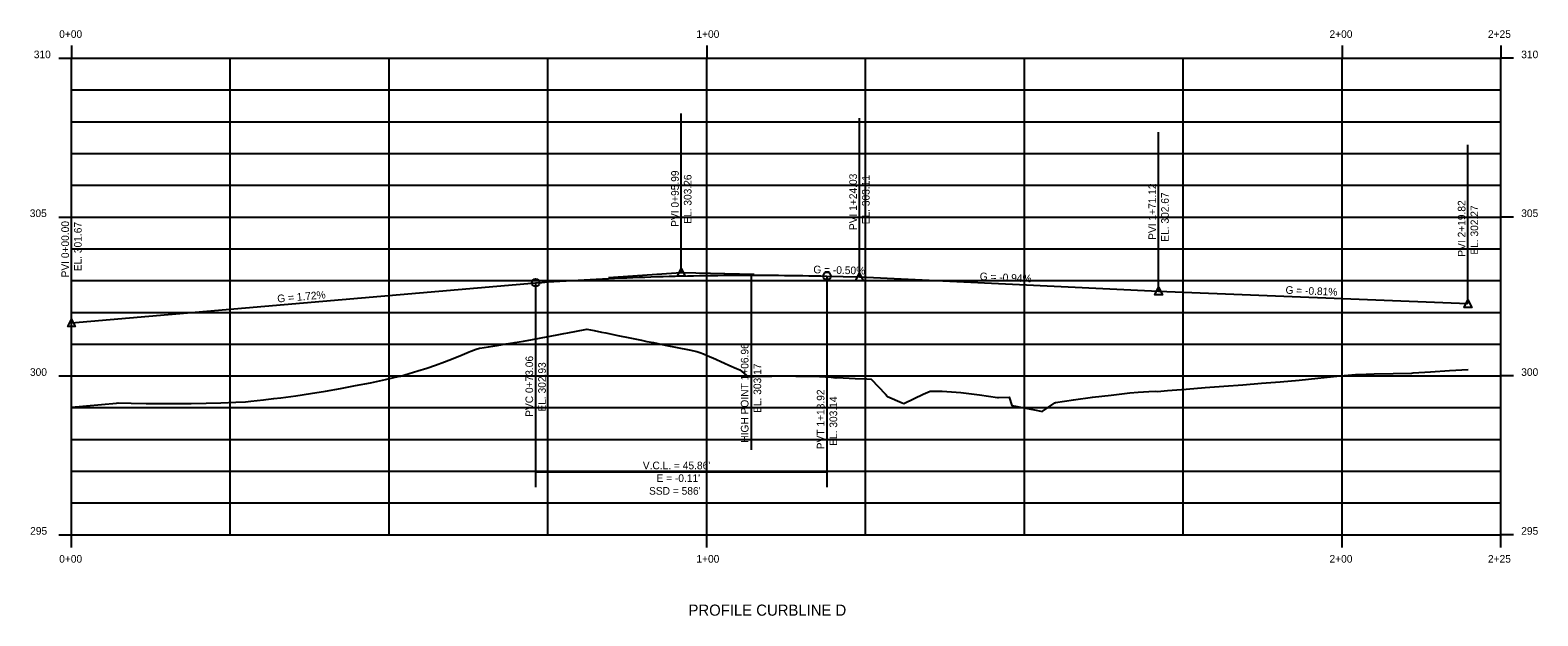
# Model space of a CAD drawing. Extents: x 916627 to 921213, y 329780 to 330157.
# Drawn here: x 920976.1 to 921213.4, y 329801.5 to 329893.7 of the extents above; entities that cross this region are included whole.
import ezdxf

# ---------------------------------------------------------------- set-up
doc = ezdxf.new("R2010")
doc.units = 0
for name, color, linetype in [('D_Roadway_Centerline', 7, 'Continuous'), ('D_Roadway_Centerline_Bearings', 7, 'Continuous'), ('D_Roadway_Centerline_CurveData', 7, 'Continuous'), ('D_Roadway_Centerline_Text', 7, 'Continuous')]:
    doc.layers.add(name, color=color, linetype=linetype)

msp = doc.modelspace()

# ---------------------------------------------------------------- linework, layer by layer
at = {"layer": 'D_Roadway_Centerline'}
for p, q in [((920982.57, 329891.28), (920982.57, 329889.28)), ((921082.57, 329891.28), (921082.57, 329889.28)), ((921182.57, 329891.28), (921182.57, 329889.28)), ((921207.57, 329891.28), (921207.57, 329889.28)), ((920980.57, 329889.28), (920982.57, 329889.28)), ((920980.57, 329889.28), (920982.57, 329889.28)), ((920982.57, 329889.28), (921207.57, 329889.28)), ((920982.57, 329814.28), (920982.57, 329889.28)), ((921082.57, 329814.28), (921082.57, 329889.28)), ((921182.57, 329814.28), (921182.57, 329889.28)), ((921209.57, 329889.28), (921207.57, 329889.28)), ((921209.57, 329889.28), (921207.57, 329889.28)), ((920980.57, 329864.28), (920982.57, 329864.28)), ((920982.57, 329864.28), (921207.57, 329864.28)), ((921209.57, 329864.28), (921207.57, 329864.28)), ((920982.57, 329847.63), (921055.63, 329853.93)), ((921101.49, 329854.98), (921106.6, 329854.86)), ((921106.6, 329854.86), (921153.69, 329852.63)), ((921153.69, 329852.63), (921202.39, 329850.66)), ((920980.57, 329839.28), (920982.57, 329839.28)), ((920982.57, 329839.28), (921207.57, 329839.28)), ((921209.57, 329839.28), (921207.57, 329839.28)), ((920980.57, 329814.28), (920982.57, 329814.28)), ((920982.57, 329812.28), (920982.57, 329814.28)), ((920982.57, 329814.28), (921207.57, 329814.28)), ((921082.57, 329812.28), (921082.57, 329814.28)), ((921182.57, 329812.28), (921182.57, 329814.28)), ((921209.57, 329814.28), (921207.57, 329814.28)), ((921207.57, 329812.28), (921207.57, 329814.28))]:
    msp.add_line(p, q, dxfattribs=at)
msp.add_lwpolyline([(921055.63, 329853.93), (921056.59, 329854), (921057.54, 329854.06), (921058.5, 329854.13), (921059.45, 329854.19), (921060.41, 329854.25), (921061.36, 329854.3), (921062.32, 329854.36), (921063.27, 329854.41), (921064.23, 329854.46), (921065.18, 329854.51), (921066.14, 329854.56), (921067.1, 329854.61), (921068.05, 329854.65), (921069.01, 329854.69), (921069.96, 329854.73), (921070.92, 329854.77), (921071.87, 329854.81), (921072.83, 329854.84), (921073.78, 329854.87), (921074.74, 329854.9), (921075.69, 329854.93), (921076.65, 329854.96), (921077.61, 329854.98), (921079.52, 329855.03), (921080.47, 329855.05), (921081.43, 329855.06), (921082.38, 329855.08), (921083.34, 329855.09), (921084.29, 329855.1), (921085.25, 329855.11), (921086.2, 329855.12), (921087.16, 329855.13), (921088.11, 329855.13), (921089.07, 329855.13), (921090.03, 329855.13), (921090.98, 329855.13), (921091.94, 329855.13), (921092.89, 329855.12), (921093.85, 329855.11), (921094.8, 329855.1), (921095.76, 329855.09), (921096.71, 329855.08), (921097.67, 329855.06), (921098.62, 329855.05), (921099.58, 329855.03), (921100.54, 329855.01), (921101.49, 329854.98)], dxfattribs=at)
at = {"layer": 'D_Roadway_Centerline_Bearings'}
msp.add_lwpolyline([(920982.57, 329834.36), (920984.92, 329834.55), (920987.28, 329834.76), (920989.63, 329835), (920989.9, 329835.02), (920991.98, 329834.97), (920994.33, 329834.94), (920996.69, 329834.92), (920999.04, 329834.93), (921001.39, 329834.95), (921003.74, 329834.99), (921006.1, 329835.06), (921008.45, 329835.14), (921009.96, 329835.21), (921010.8, 329835.29), (921012.77, 329835.49), (921013.15, 329835.54), (921014.42, 329835.71), (921015.51, 329835.84), (921017.86, 329836.16), (921020.21, 329836.5), (921022.56, 329836.88), (921024.92, 329837.29), (921027.27, 329837.74), (921029.62, 329838.21), (921031.98, 329838.72), (921034.18, 329839.22), (921034.33, 329839.26), (921035.71, 329839.65), (921037.1, 329840.07), (921038.49, 329840.51), (921039.87, 329840.99), (921041.26, 329841.5), (921042.65, 329842.03), (921044.04, 329842.6), (921045.16, 329843.08), (921045.42, 329843.17), (921046.28, 329843.47), (921046.81, 329843.65), (921046.83, 329843.66), (921048.2, 329843.87), (921049.58, 329844.08), (921050.97, 329844.3), (921052.36, 329844.54), (921053.74, 329844.77), (921055.13, 329845.02), (921056.52, 329845.27), (921057.9, 329845.53), (921059.29, 329845.8), (921060.09, 329845.96), (921060.68, 329846.06), (921062.06, 329846.31), (921063.45, 329846.56), (921063.7, 329846.61), (921064.84, 329846.4), (921065.98, 329846.18), (921066.7, 329846.04), (921068.57, 329845.66), (921070.44, 329845.28), (921072.3, 329844.89), (921073.15, 329844.71), (921074.17, 329844.51), (921076.03, 329844.14), (921077.9, 329843.76), (921079.77, 329843.37), (921081.01, 329843.11), (921081.63, 329842.89), (921081.87, 329842.81), (921082.04, 329842.76), (921083.11, 329842.28), (921083.5, 329842.11), (921085.37, 329841.3), (921086.05, 329840.99), (921087.23, 329840.46), (921087.79, 329840.21), (921089.07, 329839.14), (921089.1, 329839.14), (921090.97, 329839.21), (921092.83, 329839.25), (921094.7, 329839.27), (921096.56, 329839.26), (921098.43, 329839.23), (921100.3, 329839.17), (921102.16, 329839.09), (921102.51, 329839.07), (921102.54, 329839.05), (921102.88, 329838.96), (921102.99, 329839.05), (921104.03, 329838.99), (921105.9, 329838.89), (921107.76, 329838.79), (921108.42, 329838.75), (921110.72, 329836.42), (921111.01, 329836.02), (921113.34, 329835.03), (921113.6, 329834.92), (921113.68, 329834.96), (921116.64, 329836.42), (921117.71, 329836.89), (921119.6, 329836.85), (921122.55, 329836.65), (921125.51, 329836.32), (921128.33, 329835.89), (921128.47, 329835.9), (921130.14, 329835.94), (921130.56, 329834.62), (921131.43, 329834.47), (921134.39, 329833.88), (921135.38, 329833.65), (921137.35, 329835.02), (921137.46, 329835.1), (921140.3, 329835.51), (921143.26, 329835.91), (921146.22, 329836.27), (921149.18, 329836.6), (921150.48, 329836.73), (921152.14, 329836.81), (921153.15, 329836.85), (921153.54, 329836.83), (921155.1, 329836.96), (921158.05, 329837.19), (921161.01, 329837.43), (921163.97, 329837.66), (921166.93, 329837.89), (921169.89, 329838.11), (921172.83, 329838.33), (921172.84, 329838.33), (921175.8, 329838.63), (921178.76, 329838.92), (921181.72, 329839.21), (921184.68, 329839.49), (921185.03, 329839.52), (921187.64, 329839.59), (921190.59, 329839.67), (921193.55, 329839.73), (921193.78, 329839.74), (921196.51, 329839.93), (921199.47, 329840.12), (921202.43, 329840.3)], dxfattribs=at)
at = {"layer": 'D_Roadway_Centerline_CurveData'}
for p, q in [((921078.56, 329855.56), (921078.56, 329880.56)), ((921106.6, 329854.86), (921106.6, 329879.86)), ((921153.69, 329852.63), (921153.69, 329877.63)), ((921202.39, 329850.66), (921202.39, 329875.66)), ((920982.57, 329847.63), (920982.57, 329872.63)), ((921067.1, 329854.74), (921078.56, 329855.56)), ((921078.56, 329855.56), (921090.03, 329855.27)), ((921055.63, 329853.93), (921055.63, 329821.78)), ((921089.53, 329855.13), (921089.53, 329827.65)), ((921101.49, 329854.98), (921101.49, 329821.78))]:
    msp.add_line(p, q, dxfattribs=at)
for points in [[(921078.56, 329856.16), (921079.16, 329854.96), (921077.96, 329854.96)], [(921106.6, 329855.46), (921107.2, 329854.26), (921106, 329854.26)], [(921153.69, 329853.23), (921154.29, 329852.03), (921153.09, 329852.03)], [(921202.39, 329851.26), (921202.99, 329850.06), (921201.79, 329850.06)], [(920982.57, 329848.23), (920983.17, 329847.03), (920981.97, 329847.03)]]:
    msp.add_lwpolyline(points, close=True, dxfattribs=at)
msp.add_lwpolyline([(921055.63, 329824.18), (921101.49, 329824.18)], dxfattribs=at)
for centre in [(921101.49, 329854.98), (921055.63, 329853.93)]:
    msp.add_circle(centre, 0.6, dxfattribs=at)
at = {"layer": 'D_Roadway_Centerline_Text'}
for p, q in [((921007.57, 329814.28), (921007.57, 329889.28)), ((921032.57, 329814.28), (921032.57, 329889.28)), ((921057.57, 329814.28), (921057.57, 329889.28)), ((921107.57, 329814.28), (921107.57, 329889.28)), ((921132.57, 329814.28), (921132.57, 329889.28)), ((921157.57, 329814.28), (921157.57, 329889.28)), ((921207.57, 329814.28), (921207.57, 329889.28)), ((920982.57, 329884.28), (921207.57, 329884.28)), ((920982.57, 329879.28), (921207.57, 329879.28)), ((920982.57, 329874.28), (921207.57, 329874.28)), ((920982.57, 329869.28), (921207.57, 329869.28)), ((920982.57, 329859.28), (921207.57, 329859.28)), ((920982.57, 329854.28), (921207.57, 329854.28)), ((920982.57, 329849.28), (921207.57, 329849.28)), ((920982.57, 329844.28), (921207.57, 329844.28)), ((920982.57, 329834.28), (921207.57, 329834.28)), ((920982.57, 329829.28), (921207.57, 329829.28)), ((920982.57, 329824.28), (921207.57, 329824.28)), ((920982.57, 329819.28), (921207.57, 329819.28))]:
    msp.add_line(p, q, dxfattribs=at)

# ---------------------------------------------------------------- texts
at = {"layer": 'D_Roadway_Centerline'}
for s, p in [('HIGH POINT 1+06.96', (921089.13, 329828.76)), ('EL. 303.17', (921091.13, 329833.45))]:
    msp.add_text(s, height=1.2, rotation=90, dxfattribs=at).set_placement(p)
at = {"layer": 'D_Roadway_Centerline_CurveData'}
for s, height, p in [('0+00', 1.2, (920980.63, 329892.48)), ('1+00', 1.2, (921080.93, 329892.48)), ('2+00', 1.2, (921180.59, 329892.48)), ('2+25', 1.2, (921205.53, 329892.48)), ('310', 1.2, (920976.63, 329889.28)), ('310', 1.2, (920976.63, 329889.28)), ('310', 1.2, (921210.77, 329889.28)), ('310', 1.2, (921210.77, 329889.28)), ('305', 1.2, (920976, 329864.28)), ('305', 1.2, (921210.77, 329864.28)), ('300', 1.2, (920976.03, 329839.28)), ('300', 1.2, (921210.77, 329839.28)), ("V.C.L. = 45.86'", 1.2, (921072.5, 329824.58)), ("E = -0.11'", 1.2, (921074.65, 329822.58)), ("SSD = 586'", 1.2, (921073.48, 329820.58)), ('295', 1.2, (920976.06, 329814.28)), ('295', 1.2, (921210.77, 329814.28)), ('0+00', 1.2, (920980.63, 329809.88)), ('1+00', 1.2, (921080.93, 329809.88)), ('2+00', 1.2, (921180.59, 329809.88)), ('2+25', 1.2, (921205.53, 329809.88)), ('PROFILE CURBLINE D', 1.75, (921079.69, 329801.53))]:
    msp.add_text(s, height=height, dxfattribs=at).set_placement(p)
for s, rotation, p in [('PVI 0+95.99', 90, (921078.16, 329862.74)), ('EL. 303.26', 90, (921080.16, 329863.22)), ('PVI 1+24.03', 90, (921106.2, 329862.23)), ('EL. 303.11', 90, (921108.2, 329863.14)), ('PVI 1+71.12', 90, (921153.29, 329860.69)), ('EL. 302.67', 90, (921155.29, 329860.4)), ('PVI 2+19.82', 90, (921201.99, 329858.04)), ('EL. 302.27', 90, (921203.99, 329858.36)), ('PVI 0+00.00', 90, (920982.17, 329854.78)), ('EL. 301.67', 90, (920984.17, 329855.75)), ('G = -0.50%', 358.5679, (921099.33, 329855.44)), ('G = -0.94%', 357.296, (921125.51, 329854.37)), ('G = -0.81%', 357.6751, (921173.65, 329852.22)), ('G = 1.72%', 4.9276, (921015.01, 329850.83)), ('PVC 0+73.06', 90, (921055.23, 329832.83)), ('EL. 302.93', 90, (921057.23, 329833.66)), ('PVT 1+18.92', 90, (921101.09, 329827.73)), ('EL. 303.14', 90, (921103.09, 329828.27))]:
    msp.add_text(s, height=1.2, rotation=rotation, dxfattribs=at).set_placement(p)

doc.saveas('drawing.dxf')
